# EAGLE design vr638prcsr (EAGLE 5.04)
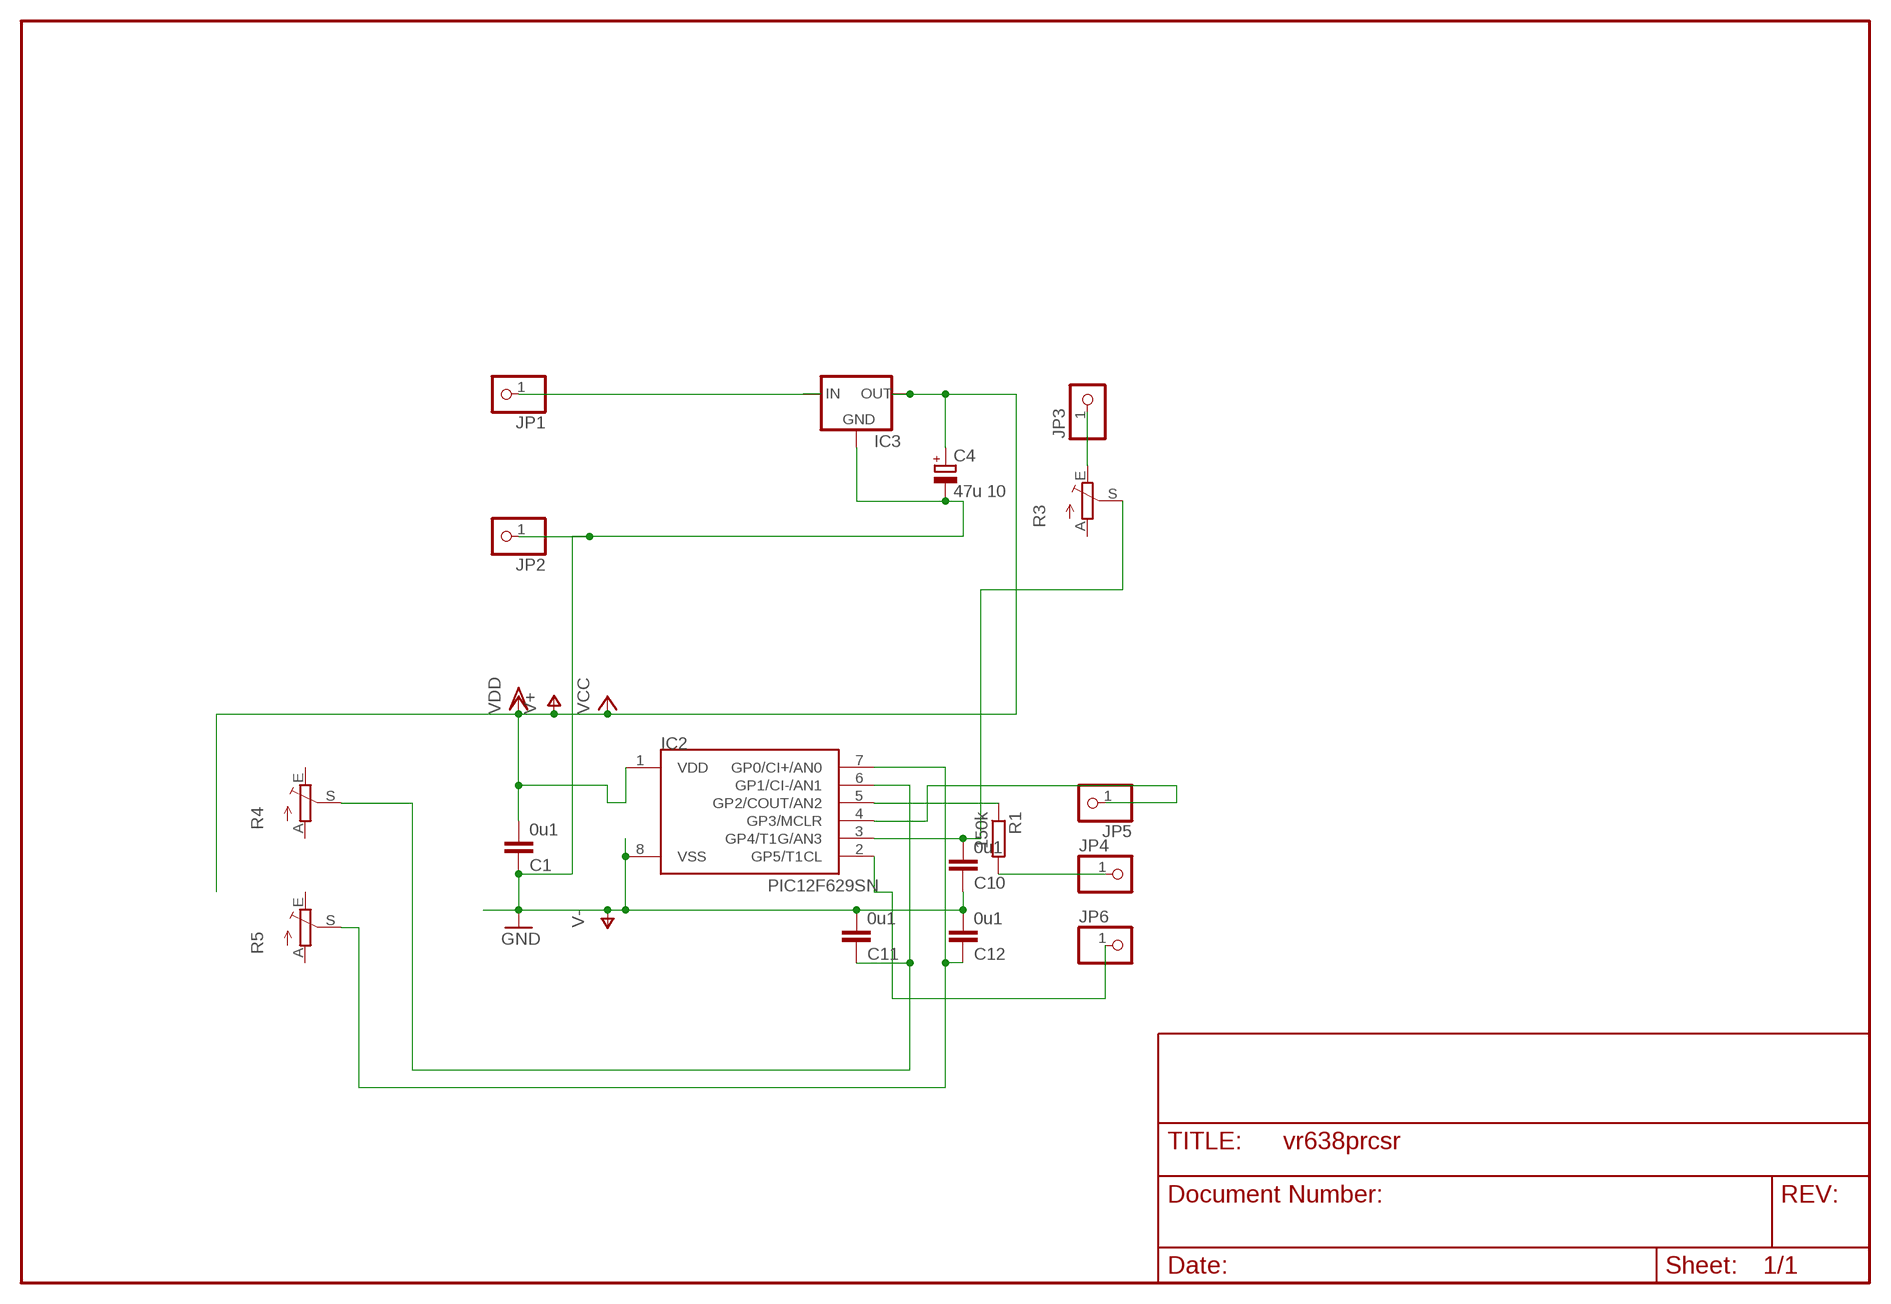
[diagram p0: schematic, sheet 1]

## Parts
C1  0u1  C-EUC1206  [C1206]
C4  47u 10  CPOL-EUE2.5-6  [E2,5-6]
C10  0u1  C-EUC1206  [C1206]
C11  0u1  C-EUC1206  [C1206]
C12  0u1  C-EUC1206  [C1206]
IC2  PIC12F629SN  [SO-08]
IC3  78LXX  [78LXX]
JP1  PINHD-1X1  [1X01]
JP2  PINHD-1X1  [1X01]
JP3  PINHD-1X1  [1X01]
JP4  PINHD-1X1  [1X01]
JP5  PINHD-1X1  [1X01]
JP6  PINHD-1X1  [1X01]
R1  150k  R-EU_R1206  [R1206]
R3  TRIM_EU-CA6V  [CA6V]
R4  TRIM_EU-CA6V  [CA6V]
R5  TRIM_EU-CA6V  [CA6V]

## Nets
N$1: JP3.1 R3.E
N$2: JP4.1 R1.2
N$3: IC2.4(GP3/MCLR) JP5.1
N$5: IC2.5(GP2/COUT/AN2) R1.1
N$8: IC2.2(GP5/T1CL) JP6.1
N$12: C10.2 IC2.3(GP4/T1G/AN3) R3.S
N$13: C12.1 IC2.7(GP0/CI+/AN0) R5.S
N$15: C11.1 IC2.6(GP1/CI-/AN1) R4.S
N$20: IC3.IN JP1.1
V+: C1.2 C4.+ IC2.1(VDD) IC3.OUT ; supply symbol labelled VCC, VDD
V-: C1.1 C4.- C10.1 C11.2 C12.2 IC2.8(VSS) IC3.GND JP2.1 ; supply symbol labelled GND
Unconnected: R3.A R4.A R4.E R5.A R5.E

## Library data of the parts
C1 C10-C12 = rcl:C-EU: CAPACITOR, European symbol
C4 = rcl:CPOL-EU: POLARIZED CAPACITOR, European symbol
IC2 = microchip-3:PIC12F6*: uPC nW 1k Program Flash memory 2x Timer Comparator 10b A/D converter/ 4xIN
IC3 = v-reg:78LXX: VOLTAGE REGULATOR
JP1-JP6 = pinhead:PINHD-1X1: PIN HEADER
R1 = rcl:R-EU_: RESISTOR, European symbol
R3-R5 = pot:TRIM_EU-: POTENTIOMETER

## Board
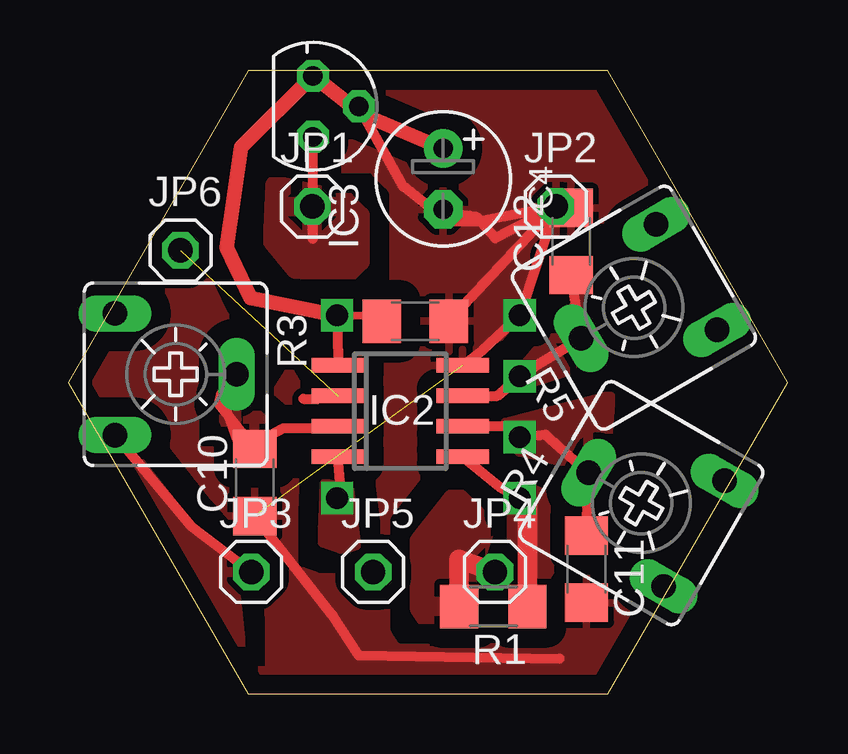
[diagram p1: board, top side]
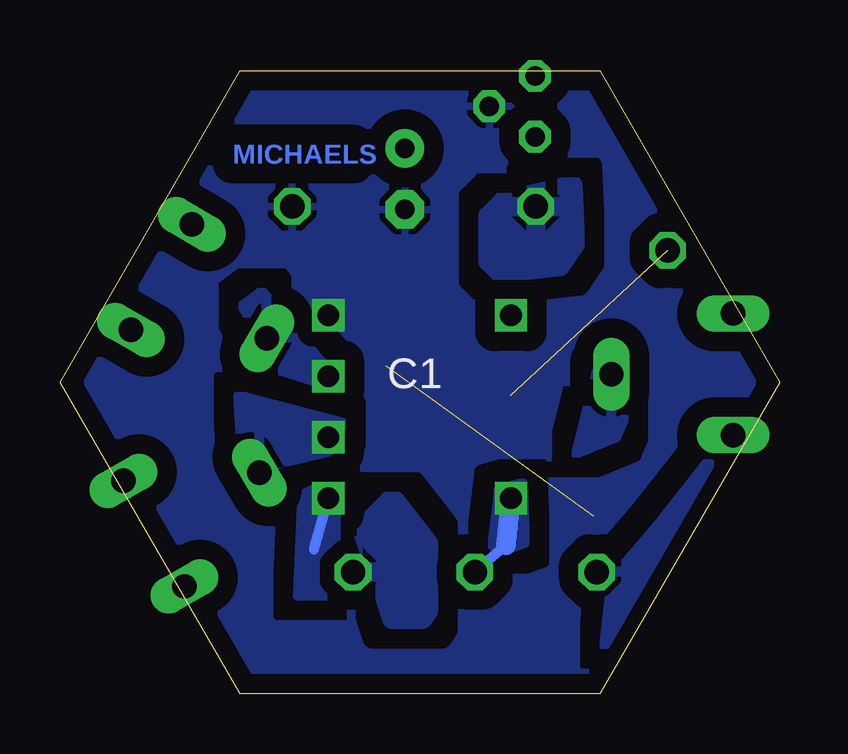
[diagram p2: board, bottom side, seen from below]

Size 30 x 25.98 mm. Coordinates in mm from the lower left corner, seen from the top.
Outline: 7.5,0 22.5,0 30,12.99 22.5,25.98 7.5,25.98 0,12.99 7.5,0
Copper layers (1*16): Top 0.035mm / dielectric 1.5mm / Bottom 0.035mm
Design rules "default *": minimum track width 10mil, minimum drill 24mil, track to track 8mil, track to pad 8mil, pad to pad 8mil, via to via 8mil, smd to smd 8mil, copper to edge 10mil, drill to drill 8mil, minimum pad ring 10mil, minimum via ring 8mil, stop-mask expansion 4mil, vias tented up to drill 0mil, thermal gap 10mil

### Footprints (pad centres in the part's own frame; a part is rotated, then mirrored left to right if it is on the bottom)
C1206 = smd 1.6 x 1.8: 1 -1.4,0; 2 1.4,0
E2,5-6 = drill 0.813 pad 1.6 round: + -1.27,0 | drill 0.813 pad 1.6 octagon: - 1.27,0
SO-08 = smd 0.6 x 2.2: 1 -1.905,-2.6; 2 -0.635,-2.6; 3 0.635,-2.6; 4 1.905,-2.6; 5 1.905,2.6; 6 0.635,2.6; 7 -0.635,2.6; 8 -1.905,2.6
78LXX = drill 0.813 octagon: GND 0,1.905; IN 1.27,0; OUT -1.27,0
1X01 = drill 1.016 octagon: 1 0,0
R1206 = smd 1.6 x 1.803: 1 -1.422,0; 2 1.422,0
CA6V = drill 1.016 long: A -2.54,-2.54; E 2.54,-2.54; S 0,2.54

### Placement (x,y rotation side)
C1  14.46,15.54 180 top
C4  15.62,21.47 270 top
C10  7.77,8.81 90 top
C11  21.59,5.2 270 top
C12  20.96,18.86 90 top
IC2  13.84,11.79 270 top
IC3  10.2,24.5 270 top
JP1  10.16,20.32 0 top
JP2  20.32,20.32 0 top
JP3  7.62,5.08 0 top
JP4  17.78,5.08 0 top
JP5  12.7,5.08 0 top
JP6  4.67,18.49 0 top
R1  17.71,3.65 180 top
R3  4.47,13.33 270 top
R4  23.88,7.95 60 top
R5  23.58,16.1 120 top

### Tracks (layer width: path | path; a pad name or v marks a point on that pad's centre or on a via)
N$1
  Top 0.406: JP3.1 5.1,7 R3.E
  pour Top (isolate 0.61): 2.1,10.8 7.2,2.1 6.9,4.9 5,7.1
  pour Bottom (isolate 0.61): 2.2,10.7 7.3,2 7,4.8 5.1,7
N$2
  Top 0.813: R1.2 16.29,5.61 JP4.1
  pour Top (isolate 0.813): 16.15,3.21 14.88,3.21 14.63,3.59 14.63,6.38 16.03,8.16 16.28,8.16 17.42,7.02
  pour Bottom (isolate 0.813): 16.15,3.11 14.88,3.11 14.63,3.49 14.63,6.28 16.03,8.06 16.28,8.06 17.42,6.92
N$3  (via drill 0.9)
  Top 0.406: IC2.4 11.36,8.32 v11.2,8.16
  Bottom 0.406: 11.4,6.19 JP5.1
  Bottom 0.813: 11.4,6.19 v11.2,8.16
  pour Top (isolate 0.61): 10.7,8.8 11.7,8.5 12,6.2 11.4,6 10.6,6.3
  pour Bottom (isolate 0.61): 10.7,8.8 11.7,8.5 12,6.2 11.4,6 10.6,6.3
N$4
  pour Top (isolate 0.254): 9.8,12.4 9.4,12 8.7,12.6 9.2,13.4
N$5  (via drill 0.9)
  Top 0.406: IC2.5 17.98,8.62 v18.82,8.16
  Top 0.813: R1.1 19.14,7.84 v18.82,8.16
  Bottom 0.406: v18.82,8.16 19.42,6.02
  pour Top (isolate 0.61): 19.1,8.7 19.9,8.3 20.1,4.1 18.5,4.1 18.5,7.6
  pour Bottom (isolate 0.61): 19.1,8.7 19.9,8.3 20.1,4.1 18.5,4.1 18.5,7.6
N$7
  Top 0.406: 9.8,12.3 10.4,12.3
N$8  (1 unrouted)
N$12
  Top 0.406: 6.36,12.49 7.2,10.12 8.96,11.08 11.16,11.08 IC2.3 | 6.36,12.49 R3.S | C10.2 6.27,12.08 6.36,12.49
  pour Top (isolate 0.61, rank 2): 7.3,13.4 8.8,10.8 6.8,10.7 6,12.5
  pour Bottom (isolate 0.61): 7.6,13.6 8.5,10 6.8,10.7 6,12.5
N$13  (via drill 0.9)
  Top 0.406: IC2.7 17.88,12.43 v18.82,13.24 19.29,13.71 | 18.9,13.1 19.5,13.7 R5.S C12.1
  pour Top (isolate 0.61): 19,12.9 20.9,13.5 22.4,16.2 21.6,16.8 18.4,13
  pour Bottom (isolate 0.61): 19,12.9 20.9,13.5 22.4,16.2 21.6,16.8 18.4,13
N$15  (via drill 0.9)
  Top 0.406: IC2.6 19.02,11.16 v18.82,10.7 | v18.82,10.7 18.93,10.59 | C11.1 R4.S 19.9,10.8 v18.82,10.7
  pour Top (isolate 0.61, rank 2): 18.2,11.3 22.4,12.4 22.6,12.4 22.4,9.8 21.7,9.4 18.8,10.1
  pour Bottom (isolate 0.61, rank 2): 18.2,11.3 22.4,12.4 22.6,12.4 22.4,9.8 21.7,9.4 18.8,10.1
N$20
  Top 0.406: IC3.IN 10.2,18.98 JP1.1
  pour Top (isolate 0.813): 8.61,21.21 8.51,18.88 9.46,17.72 11.66,17.52 12.16,18.03 12.16,19.94 11.53,20.57
  pour Bottom (isolate 0.813): 8.61,21.21 8.51,18.78 9.16,17.82 11.66,17.52 12.16,18.03 12.16,19.94 11.53,20.57
V+  (via drill 0.9)
  Top 0.305: v11.2,15.78 13.45,15.78 C1.2
  Top 0.406: IC2.1 11.23,15.1 11.3,15.7 v11.2,15.78
  Top 0.61: C4.+ 12.2,24.2 IC3.OUT 7.2,22.8 6.6,18.6 7.6,16.5 v11.2,15.78
V-  (via drill 0.9)  (1 unrouted)
  Top 0.406: IC2.8 17.26,14.32 v18.82,15.78 JP2.1 | IC3.GND 13.94,21.16 15.8,19.7 17.1,19.7 JP2.1 | C4.- 16,20 17,19.9 17.8,19 JP2.1 | JP2.1 C1.1 | C10.1 11,3.3 12.1,1.6 20.47,1.47
  pour Top (isolate 0.813, rank 4): 22.85,25.64 30.02,13.23 22.99,0.25 7.24,0.65 -0.28,14.57 8.01,25.74
  pour Bottom (isolate 0.813, rank 4): 22.69,0.45 6.94,0.85 -0.63,14.71 7.44,25.75 23.4,26.48 24.95,23.34 29.84,13.01

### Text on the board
Bottom: MICHAELS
